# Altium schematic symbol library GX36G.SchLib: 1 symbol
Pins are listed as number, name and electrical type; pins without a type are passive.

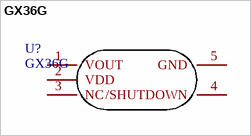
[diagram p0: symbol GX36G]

## GX36G
designator U?
footprint SOT-23-5
pins: 1 VOUT, 2 VDD, 3 NC, 4 /SHUTDOWN, 5 GND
